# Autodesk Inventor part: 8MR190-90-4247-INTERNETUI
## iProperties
Created: 2010-01
Part Number: 8MR190-90-4247-INTERNETUI
Document SubType Name: Modeling
Designer: Darius
Author: Darius
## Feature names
1. Base1
